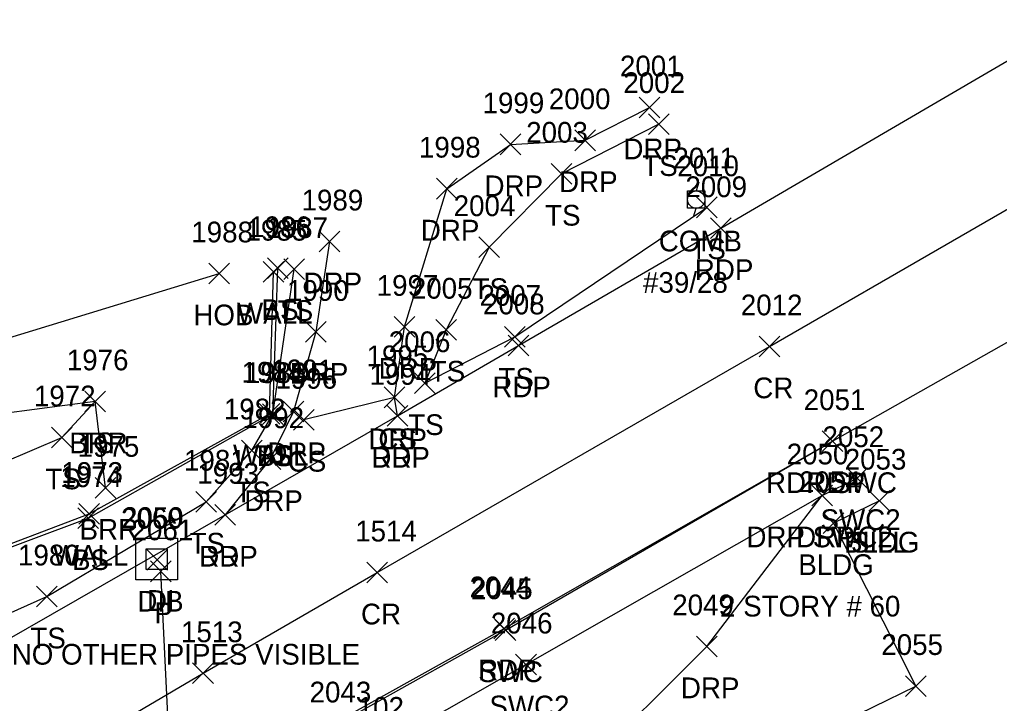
# Model space of a CAD drawing. Extents: x 1657482 to 1661439, y 647981 to 649041.
# Drawn here: x 1660079.4 to 1660173.9, y 648192.9 to 648258.8 of the extents above; entities that cross this region are included whole.
import ezdxf

# ---------------------------------------------------------------- set-up
doc = ezdxf.new("R2010")
doc.units = 0
for name, color, linetype in [('C_I', 7, 'Continuous'), ('D_A', 7, 'Continuous'), ('D_C', 7, 'Continuous'), ('D_I', 7, 'Continuous'), ('D_TIC', 7, 'Continuous'), ('DCP', 7, 'Continuous'), ('DS', 7, 'Continuous'), ('L_A', 7, 'Continuous'), ('L_C', 7, 'Continuous'), ('L_I', 7, 'Continuous'), ('L_TIC', 7, 'Continuous'), ('LABL', 7, 'Continuous'), ('LBC', 7, 'Continuous'), ('LELB', 7, 'Continuous'), ('LW', 7, 'Continuous'), ('P_A', 7, 'Continuous'), ('P_I', 7, 'Continuous'), ('P_TIC', 7, 'Continuous'), ('PET', 7, 'Continuous'), ('PRC', 7, 'Continuous'), ('R_A', 7, 'Continuous'), ('R_I', 7, 'Continuous'), ('R_TIC', 7, 'Continuous'), ('RDP', 7, 'Continuous'), ('RSW', 7, 'Continuous'), ('U_A', 7, 'Continuous'), ('U_C', 7, 'Continuous'), ('U_I', 7, 'Continuous'), ('UP', 7, 'Continuous')]:
    doc.layers.add(name, color=color, linetype=linetype)

msp = doc.modelspace()

# ---------------------------------------------------------------- linework, layer by layer
at = {"layer": 'D_TIC'}
for points in [[(1660091.64, 648205.719), (1660093.64, 648207.719)], [(1660093.64, 648205.719), (1660091.64, 648207.719)], [(1660092.004, 648204.604), (1660094.004, 648206.604)], [(1660094.004, 648204.604), (1660092.004, 648206.604)]]:
    msp.add_lwpolyline(points, dxfattribs=at)
at = {"layer": 'DCP'}
msp.add_lwpolyline([(1660094.024, 648184.435), (1660093.004, 648205.604)], dxfattribs=at)
at = {"layer": 'DS'}
for p, q in [((1660090.606, 648208.79), (1660094.606, 648208.79)), ((1660090.606, 648204.79), (1660090.606, 648208.79)), ((1660094.606, 648208.79), (1660094.606, 648204.79)), ((1660091.606, 648205.79), (1660091.606, 648207.79)), ((1660091.606, 648207.79), (1660093.606, 648207.79)), ((1660093.606, 648207.79), (1660093.606, 648205.79)), ((1660092.611, 648206.792), (1660092.611, 648206.792)), ((1660092.611, 648206.792), (1660092.611, 648206.792)), ((1660093.606, 648205.79), (1660091.606, 648205.79)), ((1660094.606, 648204.79), (1660090.606, 648204.79))]:
    msp.add_line(p, q, dxfattribs=at)
at = {"layer": 'L_TIC'}
for points in [[(1660140.046, 648247.747), (1660142.046, 648249.747)], [(1660142.046, 648247.747), (1660140.046, 648249.747)], [(1660130.669, 648242.956), (1660132.669, 648244.956)], [(1660132.669, 648242.956), (1660130.669, 648244.956)], [(1660144.683, 648239.72), (1660146.683, 648241.72)], [(1660146.683, 648239.72), (1660144.683, 648241.72)], [(1660123.673, 648235.873), (1660125.673, 648237.873)], [(1660125.673, 648235.873), (1660123.673, 648237.873)], [(1660097.64, 648233.34), (1660099.64, 648235.34)], [(1660099.64, 648233.34), (1660097.64, 648235.34)], [(1660102.867, 648233.508), (1660104.867, 648235.508)], [(1660104.867, 648233.508), (1660102.867, 648235.508)], [(1660103.281, 648233.845), (1660105.281, 648235.845)], [(1660105.281, 648233.845), (1660103.281, 648235.845)], [(1660104.876, 648233.759), (1660106.876, 648235.759)], [(1660106.876, 648233.759), (1660104.876, 648235.759)], [(1660119.539, 648227.907), (1660121.539, 648229.907)], [(1660121.539, 648227.907), (1660119.539, 648229.907)], [(1660126.162, 648227.223), (1660128.162, 648229.223)], [(1660128.162, 648227.223), (1660126.162, 648229.223)], [(1660117.467, 648222.752), (1660119.467, 648224.752)], [(1660119.467, 648222.752), (1660117.467, 648224.752)], [(1660085.682, 648220.996), (1660087.682, 648222.996)], [(1660087.682, 648220.996), (1660085.682, 648222.996)], [(1660085.682, 648220.996), (1660087.682, 648222.996)], [(1660087.682, 648220.996), (1660085.682, 648222.996)], [(1660114.547, 648221.39), (1660116.547, 648223.39)], [(1660116.547, 648221.39), (1660114.547, 648223.39)], [(1660102.481, 648219.811), (1660104.481, 648221.811)], [(1660104.481, 648219.811), (1660102.481, 648221.811)], [(1660102.811, 648219.76), (1660104.811, 648221.76)], [(1660104.811, 648219.76), (1660102.811, 648221.76)], [(1660102.811, 648219.76), (1660104.811, 648221.76)], [(1660104.811, 648219.76), (1660102.811, 648221.76)], [(1660105.811, 648219.222), (1660107.811, 648221.222)], [(1660107.811, 648219.222), (1660105.811, 648221.222)], [(1660082.455, 648217.52), (1660084.455, 648219.52)], [(1660084.455, 648217.52), (1660082.455, 648219.52)], [(1660100.779, 648216.262), (1660102.779, 648218.262)], [(1660102.779, 648216.262), (1660100.779, 648218.262)], [(1660086.677, 648212.657), (1660088.677, 648214.657)], [(1660088.677, 648212.657), (1660086.677, 648214.657)], [(1660096.37, 648211.316), (1660098.37, 648213.316)], [(1660098.37, 648211.316), (1660096.37, 648213.316)], [(1660161.321, 648211.418), (1660163.321, 648213.418)], [(1660163.321, 648211.418), (1660161.321, 648213.418)], [(1660161.321, 648211.418), (1660163.321, 648213.418)], [(1660163.321, 648211.418), (1660161.321, 648213.418)], [(1660085.001, 648209.727), (1660087.001, 648211.727)], [(1660087.001, 648209.727), (1660085.001, 648211.727)], [(1660085.099, 648210.139), (1660087.099, 648212.139)], [(1660087.099, 648210.139), (1660085.099, 648212.139)], [(1660156.909, 648209.247), (1660158.909, 648211.247)], [(1660158.909, 648209.247), (1660156.909, 648211.247)], [(1660081.011, 648202.174), (1660083.011, 648204.174)], [(1660083.011, 648202.174), (1660081.011, 648204.174)], [(1660164.85, 648193.537), (1660166.85, 648195.537)], [(1660166.85, 648193.537), (1660164.85, 648195.537)], [(1660164.85, 648193.537), (1660166.85, 648195.537)], [(1660166.85, 648193.537), (1660164.85, 648195.537)]]:
    msp.add_lwpolyline(points, dxfattribs=at)
at = {"layer": 'LABL'}
msp.add_lwpolyline([(1660087.677, 648213.657), (1660086.682, 648221.996), (1660071.993, 648220.063)], dxfattribs=at)
at = {"layer": 'LBC'}
for points in [[(1660072.442, 648226.339), (1660098.64, 648234.34)], [(1660162.321, 648212.418), (1660157.909, 648210.247), (1660165.85, 648194.537)]]:
    msp.add_lwpolyline(points, dxfattribs=at)
at = {"layer": 'LELB'}
for points in [[(1660141.046, 648248.747), (1660131.669, 648243.956), (1660124.673, 648236.873), (1660120.539, 648228.907), (1660118.467, 648223.752), (1660127.162, 648228.223), (1660145.683, 648240.72)], [(1660064.36, 648210.577), (1660068.177, 648204.071), (1660086.001, 648210.727), (1660103.811, 648220.76), (1660104.281, 648234.845)], [(1660071.088, 648198.291), (1660082.011, 648203.174), (1660097.37, 648212.316), (1660101.779, 648217.262), (1660103.811, 648220.76), (1660105.876, 648234.759)], [(1660058.36, 648225.618), (1660063.211, 648214.713), (1660064.36, 648210.577), (1660074.822, 648214.863), (1660083.455, 648218.52), (1660086.682, 648221.996)], [(1660115.547, 648222.39), (1660106.811, 648220.222)], [(1660062.987, 648150.882), (1660075.31, 648157.317), (1660082.438, 648164.723), (1660087.736, 648165.939), (1660091.837, 648162.237), (1660098.334, 648160.413), (1660112.982, 648168.997), (1660137.252, 648180.586), (1660165.85, 648194.537)]]:
    msp.add_lwpolyline(points, dxfattribs=at)
at = {"layer": 'LW'}
msp.add_lwpolyline([(1660064.36, 648210.577), (1660068.325, 648204.385), (1660086.099, 648211.139), (1660103.481, 648220.811), (1660103.867, 648234.508)], dxfattribs=at)
at = {"layer": 'P_TIC'}
for points in [[(1660146.036, 648237.705), (1660148.036, 648239.705)], [(1660148.036, 648237.705), (1660146.036, 648239.705)], [(1660126.502, 648226.394), (1660128.502, 648228.394)], [(1660128.502, 648226.394), (1660126.502, 648228.394)], [(1660150.727, 648226.302), (1660152.727, 648228.302)], [(1660152.727, 648226.302), (1660150.727, 648228.302)], [(1660114.826, 648219.603), (1660116.826, 648221.603)], [(1660116.826, 648219.603), (1660114.826, 648221.603)], [(1660156.801, 648217.155), (1660158.801, 648219.155)], [(1660158.801, 648217.155), (1660156.801, 648219.155)], [(1660098.221, 648210.06), (1660100.221, 648212.06)], [(1660100.221, 648210.06), (1660098.221, 648212.06)], [(1660112.884, 648204.485), (1660114.884, 648206.485)], [(1660114.884, 648204.485), (1660112.884, 648206.485)], [(1660125.126, 648199.097), (1660127.126, 648201.097)], [(1660127.126, 648199.097), (1660125.126, 648201.097)], [(1660096.076, 648194.768), (1660098.076, 648196.768)], [(1660098.076, 648194.768), (1660096.076, 648196.768)]]:
    msp.add_lwpolyline(points, dxfattribs=at)
at = {"layer": 'PET'}
for points in [[(1660001.577, 648157.024), (1660026.061, 648170.189), (1660049.305, 648182.909), (1660058.476, 648187.71), (1660070.685, 648194.717), (1660099.221, 648211.06), (1660115.826, 648220.603), (1660127.502, 648227.394), (1660147.036, 648238.705), (1660181.486, 648258.832)], [(1660002.916, 648130.398), (1660023.122, 648141.511), (1660054.019, 648158.569), (1660066.127, 648166.199), (1660084.515, 648176.384), (1660103.189, 648187.334), (1660126.126, 648200.097), (1660157.801, 648218.155), (1660193.819, 648238.551)]]:
    msp.add_lwpolyline(points, dxfattribs=at)
at = {"layer": 'PRC'}
msp.add_lwpolyline([(1659666.144, 648110.534), (1659699.551, 648107.376), (1659729.526, 648104.331), (1659765.503, 648101.141), (1659792.988, 648098.376), (1659818.732, 648097.206), (1659849.225, 648095.841), (1659870.331, 648096.361), (1659894.597, 648099.456), (1659913.112, 648103.656), (1659935.294, 648110.794), (1659956.941, 648119.929), (1659978.865, 648130.6), (1660002.085, 648142.328), (1660031.609, 648158.263), (1660061.231, 648174.691), (1660097.076, 648195.768), (1660113.884, 648205.485), (1660151.727, 648227.302), (1660188.688, 648248.658)], dxfattribs=at)
at = {"layer": 'R_TIC'}
for points in [[(1660139.147, 648249.353), (1660141.147, 648251.353)], [(1660141.147, 648249.353), (1660139.147, 648251.353)], [(1660125.746, 648245.796), (1660127.746, 648247.796)], [(1660127.746, 648245.796), (1660125.746, 648247.796)], [(1660132.937, 648246.187), (1660134.937, 648248.187)], [(1660134.937, 648246.187), (1660132.937, 648248.187)], [(1660119.602, 648241.519), (1660121.602, 648243.519)], [(1660121.602, 648241.519), (1660119.602, 648243.519)], [(1660108.285, 648236.42), (1660110.285, 648238.42)], [(1660110.285, 648236.42), (1660108.285, 648238.42)], [(1660106.96, 648227.698), (1660108.96, 648229.698)], [(1660108.96, 648227.698), (1660106.96, 648229.698)], [(1660115.524, 648228.186), (1660117.524, 648230.186)], [(1660117.524, 648228.186), (1660115.524, 648230.186)], [(1660114.547, 648221.39), (1660116.547, 648223.39)], [(1660116.547, 648221.39), (1660114.547, 648223.39)], [(1660104.805, 648220.036), (1660106.805, 648222.036)], [(1660106.805, 648220.036), (1660104.805, 648222.036)], [(1660114.826, 648219.603), (1660116.826, 648221.603)], [(1660116.826, 648219.603), (1660114.826, 648221.603)], [(1660156.801, 648217.155), (1660158.801, 648219.155)], [(1660158.801, 648217.155), (1660156.801, 648219.155)], [(1660102.568, 648215.42), (1660104.568, 648217.42)], [(1660104.568, 648215.42), (1660102.568, 648217.42)], [(1660159.174, 648213.588), (1660161.174, 648215.588)], [(1660161.174, 648213.588), (1660159.174, 648215.588)], [(1660155.807, 648211.923), (1660157.807, 648213.923)], [(1660157.807, 648211.923), (1660155.807, 648213.923)], [(1660155.807, 648211.923), (1660157.807, 648213.923)], [(1660157.807, 648211.923), (1660155.807, 648213.923)], [(1660098.221, 648210.06), (1660100.221, 648212.06)], [(1660100.221, 648210.06), (1660098.221, 648212.06)], [(1660125.268, 648198.916), (1660127.268, 648200.916)], [(1660127.268, 648198.916), (1660125.268, 648200.916)], [(1660144.687, 648197.363), (1660146.687, 648199.363)], [(1660146.687, 648197.363), (1660144.687, 648199.363)], [(1660127.233, 648195.611), (1660129.233, 648197.611)], [(1660129.233, 648195.611), (1660127.233, 648197.611)]]:
    msp.add_lwpolyline(points, dxfattribs=at)
at = {"layer": 'RDP'}
for points in [[(1660115.826, 648220.603), (1660115.547, 648222.39), (1660116.524, 648229.186), (1660120.602, 648242.519), (1660126.746, 648246.796), (1660133.937, 648247.187), (1660140.147, 648250.353)], [(1660109.285, 648237.42), (1660107.96, 648228.698), (1660105.805, 648221.036), (1660103.568, 648216.42), (1660099.221, 648211.06)], [(1660091.773, 648175.551), (1660099.665, 648171.191), (1660109.987, 648173.164), (1660133.757, 648186.469), (1660145.687, 648198.363), (1660156.807, 648212.923)]]:
    msp.add_lwpolyline(points, dxfattribs=at)
at = {"layer": 'RSW'}
for points in [[(1660054.019, 648158.569), (1660066.26, 648165.695), (1660084.779, 648176.019), (1660103.25, 648187.06), (1660126.268, 648199.916), (1660157.801, 648218.155)], [(1660058.192, 648152.49), (1660068.162, 648162.382), (1660086.381, 648172.581), (1660091.773, 648175.551), (1660105.145, 648183.473), (1660128.233, 648196.611), (1660156.807, 648212.923), (1660160.174, 648214.588)]]:
    msp.add_lwpolyline(points, dxfattribs=at)
at = {"layer": 'UP'}
for p, q in [((1660144.907, 648243.139), (1660144.657, 648242.306)), ((1660143.824, 648240.639), (1660143.824, 648242.306)), ((1660143.824, 648242.306), (1660145.49, 648242.306)), ((1660145.49, 648242.306), (1660145.49, 648240.639)), ((1660144.657, 648241.472), (1660144.657, 648241.472)), ((1660145.49, 648240.639), (1660143.824, 648240.639)), ((1660144.407, 648239.806), (1660144.657, 648240.639))]:
    msp.add_line(p, q, dxfattribs=at)
msp.add_circle((1660144.657, 648241.472), 0.833, dxfattribs=at)

# ---------------------------------------------------------------- texts
at = {"layer": 'C_I'}
msp.add_text('102', height=2, dxfattribs=at).set_placement((1660111.999, 648191.479))
at = {"layer": 'D_A'}
for s, p in [('DIB', (1660090.743, 648201.719)), ('DI', (1660091.666, 648201.792)), ('P', (1660092.382, 648200.604))]:
    msp.add_text(s, height=2, dxfattribs=at).set_placement(p)
at = {"layer": 'D_C'}
msp.add_text('12 RCP NO OTHER PIPES VISIBLE', height=2, dxfattribs=at).set_placement((1660068.516, 648196.604))
at = {"layer": 'D_I'}
for s, p in [('2060', (1660089.168, 648209.719)), ('2059', (1660089.264, 648209.792)), ('2061', (1660090.185, 648208.604))]:
    msp.add_text(s, height=2, dxfattribs=at).set_placement(p)
at = {"layer": 'L_A'}
for s, p in [('TS', (1660139.455, 648243.747)), ('TS', (1660130.079, 648238.956)), ('TS', (1660144.093, 648235.72)), ('TS', (1660123.083, 648231.873)), ('WALL', (1660100.355, 648229.508)), ('BS', (1660102.721, 648229.845)), ('TS', (1660104.286, 648229.759)), ('HOB', (1660096.144, 648229.34)), ('TS', (1660118.948, 648223.907)), ('TS', (1660125.572, 648223.223)), ('TS', (1660116.876, 648218.752)), ('CS', (1660113.988, 648217.39)), ('BRR', (1660084.17, 648216.996)), ('TS', (1660085.091, 648216.996)), ('WALL', (1660099.97, 648215.811)), ('TS', (1660102.22, 648215.76)), ('BS', (1660102.252, 648215.76)), ('CS', (1660105.252, 648215.222)), ('TS', (1660081.865, 648213.52)), ('TS', (1660100.189, 648212.262)), ('BRR', (1660085.165, 648208.657)), ('TS', (1660095.779, 648207.316)), ('BLDG', (1660158.911, 648207.418)), ('SILL', (1660159.581, 648207.418)), ('WALL', (1660082.587, 648206.139)), ('BS', (1660084.442, 648205.727)), ('BLDG', (1660154.5, 648205.247)), ('TS', (1660080.421, 648198.174))]:
    msp.add_text(s, height=2, dxfattribs=at).set_placement(p)
at = {"layer": 'L_C'}
msp.add_text('2 STORY # 60', height=2, dxfattribs=at).set_placement((1660146.957, 648201.247))
at = {"layer": 'L_I'}
for s, p in [('2002', (1660137.628, 648251.747)), ('2003', (1660128.252, 648246.956)), ('2010', (1660142.825, 648243.72)), ('2004', (1660121.256, 648239.873)), ('1988', (1660095.947, 648237.34)), ('1985', (1660101.174, 648237.508)), ('1986', (1660101.533, 648237.845)), ('1987', (1660103.184, 648237.759)), ('2005', (1660117.122, 648231.907)), ('2007', (1660123.745, 648231.223)), ('2006', (1660114.994, 648226.752)), ('1976', (1660083.934, 648224.996)), ('1976', (1660083.934, 648224.996)), ('1995', (1660112.854, 648225.39)), ('1984', (1660100.789, 648223.811)), ('1983', (1660101.118, 648223.76)), ('1983', (1660101.118, 648223.76)), ('1996', (1660104.064, 648223.222)), ('1972', (1660080.762, 648221.52)), ('1982', (1660099.086, 648220.262)), ('1975', (1660084.984, 648216.657)), ('1981', (1660095.244, 648215.316)), ('2053', (1660158.982, 648215.418)), ('2053', (1660158.982, 648215.418)), ('1974', (1660083.308, 648213.727)), ('1973', (1660083.406, 648214.139)), ('2054', (1660154.571, 648213.247)), ('1980', (1660079.232, 648206.174)), ('2055', (1660162.511, 648197.537)), ('2055', (1660162.511, 648197.537))]:
    msp.add_text(s, height=2, dxfattribs=at).set_placement(p)
at = {"layer": 'P_A'}
for s, p in [('RDP', (1660144.524, 648233.705)), ('RDP', (1660124.99, 648222.394)), ('CR', (1660150.161, 648222.302)), ('RDP', (1660113.314, 648215.603)), ('RDP', (1660155.289, 648213.155)), ('RDP', (1660096.709, 648206.06)), ('CR', (1660112.317, 648200.485)), ('RDP', (1660123.614, 648195.097))]:
    msp.add_text(s, height=2, dxfattribs=at).set_placement(p)
at = {"layer": 'P_I'}
for s, p in [('2009', (1660143.611, 648241.705)), ('2008', (1660124.084, 648230.394)), ('2012', (1660148.956, 648230.302)), ('1994', (1660113.133, 648223.603)), ('2051', (1660155.029, 648221.155)), ('1993', (1660096.528, 648214.06)), ('1514', (1660111.758, 648208.485)), ('2044', (1660122.787, 648203.097)), ('1513', (1660094.951, 648198.768))]:
    msp.add_text(s, height=2, dxfattribs=at).set_placement(p)
at = {"layer": 'R_A'}
for s, p in [('DRP', (1660137.635, 648245.353)), ('DRP', (1660124.234, 648241.796)), ('DRP', (1660131.426, 648242.187)), ('DRP', (1660118.09, 648237.519)), ('DRP', (1660106.773, 648232.42)), ('DRP', (1660114.012, 648224.186)), ('DRP', (1660105.448, 648223.698)), ('DRP', (1660113.035, 648217.39)), ('DRP', (1660103.293, 648216.036)), ('DRP', (1660113.314, 648215.603)), ('RDP SWC', (1660151.384, 648213.155)), ('DRP', (1660101.056, 648211.42)), ('SWC2', (1660156.646, 648209.588)), ('DRP SWC2', (1660149.5, 648207.923)), ('DRP', (1660154.296, 648207.923)), ('DRP', (1660096.709, 648206.06)), ('SWC', (1660123.63, 648194.916)), ('DRP', (1660143.176, 648193.363)), ('SWC2', (1660124.706, 648191.611))]:
    msp.add_text(s, height=2, dxfattribs=at).set_placement(p)
at = {"layer": 'R_I'}
for s, p in [('2001', (1660137.296, 648253.353)), ('2000', (1660130.434, 648250.187)), ('1999', (1660124.046, 648249.796)), ('1998', (1660117.91, 648245.519)), ('1989', (1660106.584, 648240.42)), ('1990', (1660105.18, 648231.698)), ('1997', (1660113.831, 648232.186)), ('1995', (1660112.854, 648225.39)), ('1991', (1660103.679, 648224.036)), ('1994', (1660113.133, 648223.603)), ('2051', (1660155.029, 648221.155)), ('1992', (1660100.875, 648219.42)), ('2052', (1660156.835, 648217.588)), ('2050', (1660153.382, 648215.923)), ('2050', (1660153.382, 648215.923)), ('1993', (1660096.528, 648214.06)), ('2045', (1660122.93, 648202.916)), ('2049', (1660142.341, 648201.363)), ('2046', (1660124.84, 648199.611))]:
    msp.add_text(s, height=2, dxfattribs=at).set_placement(p)
at = {"layer": 'U_A'}
msp.add_text('COMB', height=2, dxfattribs=at).set_placement((1660141.043, 648236.472))
at = {"layer": 'U_C'}
msp.add_text('#39/28', height=2, dxfattribs=at).set_placement((1660139.523, 648232.472))
at = {"layer": 'U_I'}
for s, p in [('2011', (1660142.453, 648244.472)), ('2043', (1660107.357, 648192.958))]:
    msp.add_text(s, height=2, dxfattribs=at).set_placement(p)

doc.saveas('drawing.dxf')
